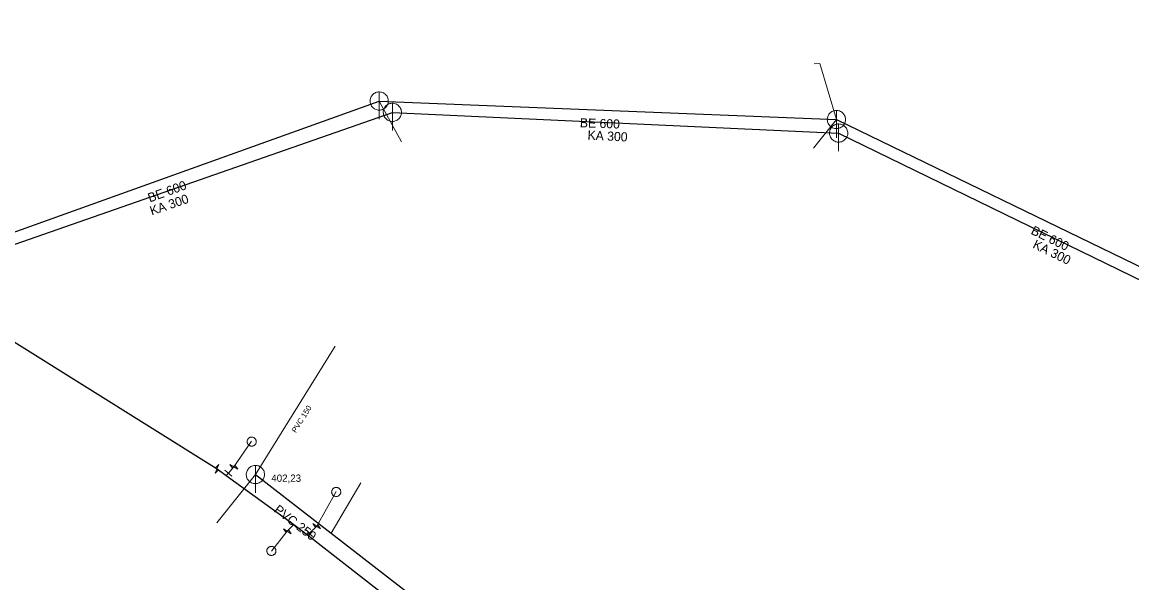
# Model space of a CAD drawing. Extents: x -809028 to -807737, y -990545 to -989489.
# Drawn here: x -808548.3 to -808426.5, y -989823.8 to -989762.3 of the extents above; entities that cross this region are included whole.
import ezdxf

# ---------------------------------------------------------------- set-up
doc = ezdxf.new("R2010")
doc.units = 0
doc.header["$LTSCALE"] = 0.32
for name, color, linetype, lineweight in [('1', 7, 'Continuous', 13), ('11', 7, 'Continuous', 13), ('13', 7, 'Continuous', 13), ('14', 7, 'Continuous', 25), ('17', 7, 'Continuous', 25), ('22', 7, 'Continuous', 13), ('23', 7, 'Continuous', 13), ('34', 7, 'Continuous', 13), ('47', 7, 'Continuous', 13)]:
    doc.layers.add(name, color=color, linetype=linetype, lineweight=lineweight)

msp = doc.modelspace()

# ---------------------------------------------------------------- linework, layer by layer
at = {"layer": '11'}
for p, q in [((-808461.4, -989766.846), (-808460.783, -989766.793)), ((-808460.783, -989766.793), (-808458.954, -989772.937)), ((-808506.67, -989775.375), (-808509.108, -989770.913)), ((-808461.474, -989776.077), (-808458.954, -989772.937)), ((-808513.956, -989797.808), (-808522.69, -989811.879)), ((-808526.908, -989817.168), (-808522.69, -989811.879)), ((-808511.142, -989812.803), (-808514.37, -989818.319))]:
    msp.add_line(p, q, dxfattribs=at)
at = {"layer": '13'}
for p, q in [((-808518.523, -989817.384), (-808519.19, -989818.1)), ((-808519.19, -989818.1), (-808520.93, -989820.29))]:
    msp.add_line(p, q, dxfattribs=at)
for points in [[(-808525.659, -989811.72), (-808525.059, -989811.03), (-808523.102, -989808.239)], [(-808516.769, -989818.299), (-808515.969, -989817.539), (-808513.833, -989813.758)]]:
    msp.add_lwpolyline(points, dxfattribs=at)
at = {"layer": '14'}
for p, q in [((-808507.662, -989772.152), (-808458.706, -989774.424)), ((-808458.954, -989772.937), (-808409.317, -989797.01)), ((-808458.706, -989774.424), (-808409.159, -989798.594))]:
    msp.add_line(p, q, dxfattribs=at)
at = {"layer": '14', "lineweight": 13}
for p, q in [((-808525.892, -989811.987), (-808525.659, -989811.72)), ((-808518.523, -989817.384), (-808518.488, -989817.344)), ((-808516.993, -989818.511), (-808516.769, -989818.299))]:
    msp.add_line(p, q, dxfattribs=at)
at = {"layer": '14'}
for points in [[(-808555.131, -989787.415), (-808509.108, -989770.913), (-808458.954, -989772.937)], [(-808583.883, -989800.875), (-808556.106, -989789.059), (-808507.662, -989772.152)], [(-808522.69, -989811.879), (-808514.37, -989818.319), (-808491.44, -989836.07), (-808464.02, -989862.219)]]:
    msp.add_lwpolyline(points, dxfattribs=at)
at = {"layer": '17'}
for points in [[(-808890.538, -989740.302), (-808584.263, -989775.39), (-808526.899, -989811.259)], [(-808526.899, -989811.259), (-808525.892, -989811.987), (-808518.488, -989817.344), (-808516.993, -989818.511), (-808509.35, -989824.46), (-808500.276, -989831.592), (-808499.949, -989831.85), (-808497.272, -989834.133), (-808490.85, -989839.61), (-808480.346, -989849.596), (-808464.346, -989864.69), (-808456.07, -989872.52), (-808448.02, -989881.399), (-808447.508, -989882.147), (-808441.27, -989891.26), (-808434.44, -989901.129), (-808434.399, -989901.41), (-808435.695, -989906.774)]]:
    msp.add_lwpolyline(points, dxfattribs=at)
at = {"layer": '22'}
for p, q in [((-808509.108, -989772.913), (-808509.107, -989769.913)), ((-808507.662, -989774.152), (-808507.661, -989771.152)), ((-808458.954, -989774.937), (-808458.953, -989771.937)), ((-808458.706, -989776.424), (-808458.705, -989773.424)), ((-808522.69, -989813.879), (-808522.689, -989810.879))]:
    msp.add_line(p, q, dxfattribs=at)
for points in [[(-808508.108, -989770.913), (-808508.113, -989770.804), (-808508.131, -989770.696), (-808508.161, -989770.59), (-808508.201, -989770.489), (-808508.253, -989770.392), (-808508.315, -989770.302), (-808508.387, -989770.219), (-808508.467, -989770.145), (-808508.555, -989770.079), (-808508.649, -989770.024), (-808508.749, -989769.979), (-808508.854, -989769.946), (-808508.961, -989769.924), (-808509.07, -989769.914), (-808509.18, -989769.916), (-808509.288, -989769.93), (-808509.395, -989769.955), (-808509.498, -989769.992), (-808509.596, -989770.041), (-808509.688, -989770.099), (-808509.774, -989770.168), (-808509.851, -989770.245), (-808509.92, -989770.331), (-808509.979, -989770.423), (-808510.027, -989770.521), (-808510.064, -989770.624), (-808510.09, -989770.731), (-808510.104, -989770.839), (-808510.107, -989770.949), (-808510.097, -989771.058), (-808510.076, -989771.165), (-808510.042, -989771.269), (-808509.998, -989771.369), (-808509.943, -989771.464), (-808509.877, -989771.552), (-808509.803, -989771.632), (-808509.72, -989771.704), (-808509.63, -989771.766), (-808509.534, -989771.818), (-808509.432, -989771.859), (-808509.327, -989771.889), (-808509.219, -989771.907), (-808509.109, -989771.913), (-808509, -989771.907), (-808508.892, -989771.889), (-808508.787, -989771.86), (-808508.685, -989771.819), (-808508.588, -989771.767), (-808508.498, -989771.705), (-808508.415, -989771.634), (-808508.34, -989771.554), (-808508.275, -989771.466), (-808508.219, -989771.372), (-808508.175, -989771.272), (-808508.141, -989771.168), (-808508.119, -989771.06), (-808508.109, -989770.951)], [(-808506.662, -989772.152), (-808506.667, -989772.043), (-808506.685, -989771.935), (-808506.715, -989771.829), (-808506.755, -989771.728), (-808506.807, -989771.631), (-808506.869, -989771.541), (-808506.941, -989771.458), (-808507.021, -989771.384), (-808507.109, -989771.318), (-808507.203, -989771.263), (-808507.303, -989771.218), (-808507.408, -989771.185), (-808507.515, -989771.163), (-808507.624, -989771.153), (-808507.734, -989771.155), (-808507.842, -989771.169), (-808507.949, -989771.194), (-808508.052, -989771.231), (-808508.15, -989771.28), (-808508.242, -989771.338), (-808508.328, -989771.407), (-808508.405, -989771.484), (-808508.474, -989771.57), (-808508.533, -989771.662), (-808508.581, -989771.76), (-808508.618, -989771.863), (-808508.644, -989771.97), (-808508.658, -989772.078), (-808508.661, -989772.188), (-808508.651, -989772.297), (-808508.63, -989772.404), (-808508.596, -989772.508), (-808508.552, -989772.608), (-808508.497, -989772.703), (-808508.431, -989772.791), (-808508.357, -989772.871), (-808508.274, -989772.943), (-808508.184, -989773.005), (-808508.088, -989773.057), (-808507.986, -989773.098), (-808507.881, -989773.128), (-808507.773, -989773.146), (-808507.663, -989773.152), (-808507.554, -989773.146), (-808507.446, -989773.128), (-808507.341, -989773.099), (-808507.239, -989773.058), (-808507.142, -989773.006), (-808507.052, -989772.944), (-808506.969, -989772.873), (-808506.894, -989772.793), (-808506.829, -989772.705), (-808506.773, -989772.611), (-808506.729, -989772.511), (-808506.695, -989772.407), (-808506.673, -989772.299), (-808506.663, -989772.19)], [(-808457.954, -989772.937), (-808457.959, -989772.828), (-808457.977, -989772.72), (-808458.007, -989772.614), (-808458.047, -989772.513), (-808458.099, -989772.416), (-808458.161, -989772.326), (-808458.233, -989772.243), (-808458.313, -989772.169), (-808458.401, -989772.103), (-808458.495, -989772.048), (-808458.595, -989772.003), (-808458.7, -989771.97), (-808458.807, -989771.948), (-808458.916, -989771.938), (-808459.026, -989771.94), (-808459.134, -989771.954), (-808459.241, -989771.979), (-808459.344, -989772.016), (-808459.442, -989772.065), (-808459.534, -989772.123), (-808459.62, -989772.192), (-808459.697, -989772.269), (-808459.766, -989772.355), (-808459.825, -989772.447), (-808459.873, -989772.545), (-808459.91, -989772.648), (-808459.936, -989772.755), (-808459.95, -989772.863), (-808459.953, -989772.973), (-808459.943, -989773.082), (-808459.922, -989773.189), (-808459.888, -989773.293), (-808459.844, -989773.393), (-808459.789, -989773.488), (-808459.723, -989773.576), (-808459.649, -989773.656), (-808459.566, -989773.728), (-808459.476, -989773.79), (-808459.38, -989773.842), (-808459.278, -989773.883), (-808459.173, -989773.913), (-808459.065, -989773.931), (-808458.955, -989773.937), (-808458.846, -989773.931), (-808458.738, -989773.913), (-808458.633, -989773.884), (-808458.531, -989773.843), (-808458.434, -989773.791), (-808458.344, -989773.729), (-808458.261, -989773.658), (-808458.186, -989773.578), (-808458.121, -989773.49), (-808458.065, -989773.396), (-808458.021, -989773.296), (-808457.987, -989773.192), (-808457.965, -989773.084), (-808457.955, -989772.975)], [(-808457.706, -989774.424), (-808457.711, -989774.315), (-808457.729, -989774.207), (-808457.759, -989774.101), (-808457.799, -989774), (-808457.851, -989773.903), (-808457.913, -989773.813), (-808457.985, -989773.73), (-808458.065, -989773.656), (-808458.153, -989773.59), (-808458.247, -989773.535), (-808458.347, -989773.49), (-808458.452, -989773.457), (-808458.559, -989773.435), (-808458.668, -989773.425), (-808458.778, -989773.427), (-808458.886, -989773.441), (-808458.993, -989773.466), (-808459.096, -989773.503), (-808459.194, -989773.552), (-808459.286, -989773.61), (-808459.372, -989773.679), (-808459.449, -989773.756), (-808459.518, -989773.842), (-808459.577, -989773.934), (-808459.625, -989774.032), (-808459.662, -989774.135), (-808459.688, -989774.242), (-808459.702, -989774.35), (-808459.705, -989774.46), (-808459.695, -989774.569), (-808459.674, -989774.676), (-808459.64, -989774.78), (-808459.596, -989774.88), (-808459.541, -989774.975), (-808459.475, -989775.063), (-808459.401, -989775.143), (-808459.318, -989775.215), (-808459.228, -989775.277), (-808459.132, -989775.329), (-808459.03, -989775.37), (-808458.925, -989775.4), (-808458.817, -989775.418), (-808458.707, -989775.424), (-808458.598, -989775.418), (-808458.49, -989775.4), (-808458.385, -989775.371), (-808458.283, -989775.33), (-808458.186, -989775.278), (-808458.096, -989775.216), (-808458.013, -989775.145), (-808457.938, -989775.065), (-808457.873, -989774.977), (-808457.817, -989774.883), (-808457.773, -989774.783), (-808457.739, -989774.679), (-808457.717, -989774.571), (-808457.707, -989774.462)], [(-808521.69, -989811.879), (-808521.695, -989811.77), (-808521.713, -989811.662), (-808521.743, -989811.556), (-808521.783, -989811.455), (-808521.835, -989811.358), (-808521.897, -989811.268), (-808521.969, -989811.185), (-808522.049, -989811.111), (-808522.137, -989811.045), (-808522.231, -989810.99), (-808522.331, -989810.945), (-808522.436, -989810.912), (-808522.543, -989810.89), (-808522.652, -989810.88), (-808522.762, -989810.882), (-808522.87, -989810.896), (-808522.977, -989810.921), (-808523.08, -989810.958), (-808523.178, -989811.007), (-808523.27, -989811.065), (-808523.356, -989811.134), (-808523.433, -989811.211), (-808523.502, -989811.297), (-808523.561, -989811.389), (-808523.609, -989811.487), (-808523.646, -989811.59), (-808523.672, -989811.697), (-808523.686, -989811.805), (-808523.689, -989811.915), (-808523.679, -989812.024), (-808523.658, -989812.131), (-808523.624, -989812.235), (-808523.58, -989812.335), (-808523.525, -989812.43), (-808523.459, -989812.518), (-808523.385, -989812.598), (-808523.302, -989812.67), (-808523.212, -989812.732), (-808523.116, -989812.784), (-808523.014, -989812.825), (-808522.909, -989812.855), (-808522.801, -989812.873), (-808522.691, -989812.879), (-808522.582, -989812.873), (-808522.474, -989812.855), (-808522.369, -989812.826), (-808522.267, -989812.785), (-808522.17, -989812.733), (-808522.08, -989812.671), (-808521.997, -989812.6), (-808521.922, -989812.52), (-808521.857, -989812.432), (-808521.801, -989812.338), (-808521.757, -989812.238), (-808521.723, -989812.134), (-808521.701, -989812.026), (-808521.691, -989811.917)]]:
    msp.add_lwpolyline(points, close=True, dxfattribs=at)
at = {"layer": '23'}
for points in [[(-808522.813, -989807.858), (-808522.858, -989807.83), (-808522.906, -989807.808), (-808522.955, -989807.792), (-808523.006, -989807.779), (-808523.057, -989807.772), (-808523.111, -989807.772), (-808523.162, -989807.776), (-808523.213, -989807.785), (-808523.264, -989807.8), (-808523.312, -989807.82), (-808523.358, -989807.845), (-808523.402, -989807.875), (-808523.441, -989807.909), (-808523.476, -989807.946), (-808523.508, -989807.987), (-808523.536, -989808.034), (-808523.558, -989808.079), (-808523.576, -989808.13), (-808523.588, -989808.179), (-808523.596, -989808.231), (-808523.595, -989808.285), (-808523.591, -989808.337), (-808523.582, -989808.389), (-808523.568, -989808.439), (-808523.547, -989808.486), (-808523.521, -989808.533), (-808523.492, -989808.575), (-808523.458, -989808.615), (-808523.419, -989808.651), (-808523.379, -989808.683), (-808523.334, -989808.71), (-808523.286, -989808.733), (-808523.237, -989808.751), (-808523.186, -989808.763), (-808523.135, -989808.768), (-808523.083, -989808.77), (-808523.03, -989808.766), (-808522.978, -989808.756), (-808522.928, -989808.741)], [(-808523.576, -989808.13), (-808523.588, -989808.179), (-808523.596, -989808.231), (-808523.595, -989808.285), (-808523.591, -989808.337), (-808523.582, -989808.389), (-808523.568, -989808.439), (-808523.547, -989808.486), (-808523.521, -989808.533), (-808523.492, -989808.575), (-808523.458, -989808.615), (-808523.419, -989808.651), (-808523.379, -989808.683), (-808523.334, -989808.71), (-808523.286, -989808.733), (-808523.237, -989808.751), (-808523.186, -989808.763), (-808523.135, -989808.768), (-808523.083, -989808.77), (-808523.03, -989808.766), (-808522.978, -989808.756), (-808522.928, -989808.741), (-808522.881, -989808.722), (-808522.834, -989808.696), (-808522.791, -989808.668), (-808522.751, -989808.632), (-808522.716, -989808.594), (-808522.684, -989808.553), (-808522.657, -989808.508), (-808522.634, -989808.461), (-808522.616, -989808.411), (-808522.605, -989808.361), (-808522.598, -989808.308), (-808522.596, -989808.257), (-808522.602, -989808.204), (-808522.61, -989808.153), (-808522.625, -989808.104), (-808522.645, -989808.054), (-808522.671, -989808.008), (-808522.7, -989807.965)], [(-808522.928, -989808.741), (-808522.881, -989808.722), (-808522.834, -989808.696), (-808522.791, -989808.668), (-808522.751, -989808.632), (-808522.716, -989808.594), (-808522.684, -989808.553), (-808522.657, -989808.508), (-808522.634, -989808.461), (-808522.616, -989808.411), (-808522.605, -989808.361), (-808522.598, -989808.308), (-808522.596, -989808.257), (-808522.602, -989808.204), (-808522.61, -989808.153), (-808522.625, -989808.104), (-808522.645, -989808.054), (-808522.671, -989808.008), (-808522.7, -989807.965), (-808522.735, -989807.926), (-808522.772, -989807.89), (-808522.813, -989807.858), (-808522.858, -989807.83), (-808522.906, -989807.808), (-808522.955, -989807.792), (-808523.006, -989807.779), (-808523.057, -989807.772), (-808523.111, -989807.772), (-808523.162, -989807.776), (-808523.213, -989807.785), (-808523.264, -989807.8), (-808523.312, -989807.82), (-808523.358, -989807.845), (-808523.402, -989807.875), (-808523.441, -989807.909), (-808523.476, -989807.946), (-808523.508, -989807.987), (-808523.536, -989808.034), (-808523.558, -989808.079), (-808523.576, -989808.13)], [(-808522.7, -989807.965), (-808522.735, -989807.926), (-808522.772, -989807.89), (-808522.813, -989807.858)], [(-808513.583, -989813.351), (-808513.63, -989813.327), (-808513.68, -989813.31), (-808513.73, -989813.299), (-808513.782, -989813.291), (-808513.834, -989813.289), (-808513.887, -989813.294), (-808513.938, -989813.303), (-808513.988, -989813.317), (-808514.036, -989813.337), (-808514.082, -989813.361), (-808514.126, -989813.39), (-808514.167, -989813.425), (-808514.203, -989813.462), (-808514.234, -989813.503), (-808514.262, -989813.547), (-808514.285, -989813.596), (-808514.303, -989813.643), (-808514.315, -989813.696), (-808514.323, -989813.746), (-808514.325, -989813.799), (-808514.32, -989813.852), (-808514.311, -989813.903), (-808514.296, -989813.954), (-808514.277, -989814.003), (-808514.252, -989814.048), (-808514.222, -989814.091), (-808514.189, -989814.131), (-808514.151, -989814.167), (-808514.109, -989814.199), (-808514.065, -989814.227), (-808514.018, -989814.25), (-808513.968, -989814.268), (-808513.917, -989814.28), (-808513.866, -989814.288), (-808513.815, -989814.288), (-808513.762, -989814.284), (-808513.71, -989814.276), (-808513.659, -989814.261), (-808513.611, -989814.241)], [(-808514.315, -989813.696), (-808514.323, -989813.746), (-808514.325, -989813.799), (-808514.32, -989813.852), (-808514.311, -989813.903), (-808514.296, -989813.954), (-808514.277, -989814.003), (-808514.252, -989814.048), (-808514.222, -989814.091), (-808514.189, -989814.131), (-808514.151, -989814.167), (-808514.109, -989814.199), (-808514.065, -989814.227), (-808514.018, -989814.25), (-808513.968, -989814.268), (-808513.917, -989814.28), (-808513.866, -989814.288), (-808513.815, -989814.288), (-808513.762, -989814.284), (-808513.71, -989814.276), (-808513.659, -989814.261), (-808513.611, -989814.241), (-808513.566, -989814.217), (-808513.522, -989814.187), (-808513.482, -989814.154), (-808513.446, -989814.115), (-808513.415, -989814.074), (-808513.386, -989814.03), (-808513.364, -989813.983), (-808513.346, -989813.934), (-808513.333, -989813.882), (-808513.327, -989813.831), (-808513.324, -989813.778), (-808513.328, -989813.727), (-808513.338, -989813.675), (-808513.352, -989813.625), (-808513.372, -989813.577), (-808513.396, -989813.529), (-808513.426, -989813.486), (-808513.46, -989813.447)], [(-808513.611, -989814.241), (-808513.566, -989814.217), (-808513.522, -989814.187), (-808513.482, -989814.154), (-808513.446, -989814.115), (-808513.415, -989814.074), (-808513.386, -989814.03), (-808513.364, -989813.983), (-808513.346, -989813.934), (-808513.333, -989813.882), (-808513.327, -989813.831), (-808513.324, -989813.778), (-808513.328, -989813.727), (-808513.338, -989813.675), (-808513.352, -989813.625), (-808513.372, -989813.577), (-808513.396, -989813.529), (-808513.426, -989813.486), (-808513.46, -989813.447), (-808513.498, -989813.411), (-808513.539, -989813.379), (-808513.583, -989813.351), (-808513.63, -989813.327), (-808513.68, -989813.31), (-808513.73, -989813.299), (-808513.782, -989813.291), (-808513.834, -989813.289), (-808513.887, -989813.294), (-808513.938, -989813.303), (-808513.988, -989813.317), (-808514.036, -989813.337), (-808514.082, -989813.361), (-808514.126, -989813.39), (-808514.167, -989813.425), (-808514.203, -989813.462), (-808514.234, -989813.503), (-808514.262, -989813.547), (-808514.285, -989813.596), (-808514.303, -989813.643), (-808514.315, -989813.696)], [(-808513.46, -989813.447), (-808513.498, -989813.411), (-808513.539, -989813.379), (-808513.583, -989813.351)], [(-808520.462, -989820.426), (-808520.447, -989820.378), (-808520.437, -989820.326), (-808520.434, -989820.272), (-808520.435, -989820.22), (-808520.441, -989820.168), (-808520.452, -989820.117), (-808520.47, -989820.069), (-808520.493, -989820.021), (-808520.519, -989819.977), (-808520.551, -989819.935), (-808520.588, -989819.897), (-808520.626, -989819.862), (-808520.669, -989819.832), (-808520.715, -989819.807), (-808520.764, -989819.786), (-808520.813, -989819.771), (-808520.864, -989819.763), (-808520.917, -989819.758), (-808520.969, -989819.758), (-808521.022, -989819.765), (-808521.073, -989819.777), (-808521.121, -989819.794), (-808521.169, -989819.817), (-808521.214, -989819.843), (-808521.256, -989819.876), (-808521.293, -989819.912), (-808521.327, -989819.95), (-808521.357, -989819.994), (-808521.383, -989820.039), (-808521.403, -989820.088), (-808521.418, -989820.138), (-808521.428, -989820.19), (-808521.433, -989820.241), (-808521.43, -989820.294), (-808521.425, -989820.345), (-808521.413, -989820.396), (-808521.396, -989820.446), (-808521.373, -989820.494), (-808521.346, -989820.538)], [(-808521.073, -989819.777), (-808521.121, -989819.794), (-808521.169, -989819.817), (-808521.214, -989819.843), (-808521.256, -989819.876), (-808521.293, -989819.912), (-808521.327, -989819.95), (-808521.357, -989819.994), (-808521.383, -989820.039), (-808521.403, -989820.088), (-808521.418, -989820.138), (-808521.428, -989820.19), (-808521.433, -989820.241), (-808521.43, -989820.294), (-808521.425, -989820.345), (-808521.413, -989820.396), (-808521.396, -989820.446), (-808521.373, -989820.494), (-808521.346, -989820.538), (-808521.314, -989820.579), (-808521.279, -989820.617), (-808521.24, -989820.652), (-808521.197, -989820.683), (-808521.15, -989820.708), (-808521.103, -989820.727), (-808521.052, -989820.742), (-808521.001, -989820.752), (-808520.948, -989820.756), (-808520.896, -989820.755), (-808520.845, -989820.749), (-808520.794, -989820.737), (-808520.745, -989820.72), (-808520.697, -989820.698), (-808520.651, -989820.67), (-808520.61, -989820.639), (-808520.573, -989820.603), (-808520.538, -989820.565), (-808520.508, -989820.52), (-808520.483, -989820.476), (-808520.462, -989820.426)], [(-808521.24, -989820.652), (-808521.197, -989820.683), (-808521.15, -989820.708), (-808521.103, -989820.727), (-808521.052, -989820.742), (-808521.001, -989820.752), (-808520.948, -989820.756), (-808520.896, -989820.755), (-808520.845, -989820.749), (-808520.794, -989820.737), (-808520.745, -989820.72), (-808520.697, -989820.698), (-808520.651, -989820.67), (-808520.61, -989820.639), (-808520.573, -989820.603), (-808520.538, -989820.565), (-808520.508, -989820.52), (-808520.483, -989820.476), (-808520.462, -989820.426), (-808520.447, -989820.378), (-808520.437, -989820.326), (-808520.434, -989820.272), (-808520.435, -989820.22), (-808520.441, -989820.168), (-808520.452, -989820.117), (-808520.47, -989820.069), (-808520.493, -989820.021), (-808520.519, -989819.977), (-808520.551, -989819.935), (-808520.588, -989819.897), (-808520.626, -989819.862), (-808520.669, -989819.832), (-808520.715, -989819.807), (-808520.764, -989819.786), (-808520.813, -989819.771), (-808520.864, -989819.763), (-808520.917, -989819.758), (-808520.969, -989819.758), (-808521.022, -989819.765), (-808521.073, -989819.777)], [(-808521.346, -989820.538), (-808521.314, -989820.579), (-808521.279, -989820.617), (-808521.24, -989820.652)]]:
    msp.add_lwpolyline(points, dxfattribs=at)
at = {"layer": '34'}
for p, q in [((-808526.036, -989811.392), (-808525.281, -989812.048)), ((-808518.892, -989817.046), (-808518.154, -989817.721)), ((-808517.113, -989817.936), (-808516.424, -989818.661))]:
    msp.add_line(p, q, dxfattribs=at)
at = {"layer": '47'}
for p, q in [((-808526.686, -989810.796), (-808527.062, -989811.141)), ((-808525.5, -989810.776), (-808525.19, -989811.181)), ((-808516.384, -989817.243), (-808516.114, -989817.677)), ((-808518.757, -989818.369), (-808519.053, -989817.952))]:
    msp.add_line(p, q, dxfattribs=at)
for points in [[(-808526.686, -989810.796), (-808527.111, -989811.721), (-808526.735, -989811.376)], [(-808525.5, -989810.776), (-808524.617, -989811.283), (-808524.927, -989810.878)], [(-808516.384, -989817.243), (-808515.553, -989817.834), (-808515.823, -989817.4)], [(-808518.757, -989818.369), (-808519.622, -989817.83), (-808519.326, -989818.247)]]:
    msp.add_lwpolyline(points, dxfattribs=at)

# ---------------------------------------------------------------- texts
at = {"layer": '1'}
for s, height, rotation, p in [('BE 600', 1, 358, (-808487.108, -989773.787)), ('KA 300', 1, 357, (-808486.272, -989775.132)), ('BE 600', 1, 20, (-808534.273, -989782.045)), ('KA 300', 1, 19, (-808534.061, -989783.468)), ('BE 600', 1, 334, (-808437.701, -989785.45)), ('KA 300', 1, 334, (-808437.499, -989786.978)), ('PVC 150 ', 0.6, 58, (-808518.248, -989807.361)), ('PVC 250 ', 1, 322, (-808520.732, -989815.904))]:
    msp.add_text(s, height=height, rotation=rotation, dxfattribs=at).set_placement(p)
at = {"layer": '14'}
msp.add_text('402,23', height=0.8, dxfattribs=at).set_placement((-808520.947, -989812.68))

doc.saveas('drawing.dxf')
